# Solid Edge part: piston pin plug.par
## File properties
Author: Robert a Rhodes jr
Template: Normal.par
Last saved by: Cadcim
Revision: 5
Application: Solid Edge
Accuracy: 0.99
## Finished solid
Body 1: solid body, 6 faces, 5 edges, 0 vertices.
  Faces by surface: plane 3, cylinder 2, torus 1
  Edges by curve: circle 5
Bounding box of the edges (mm; curved faces can reach further): 22.000 x 22.000 x 15.000, from (-11, -11, -12) to (11, 11, 3).
Cylindrical faces by radius (mm): R5.5 x1, R11 x1
Toroidal faces (ring radius, tube radius in mm): R9 r2 x1
Planar faces by outward normal: +z 1, -z 2
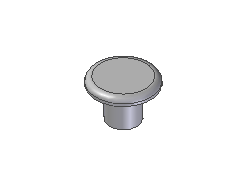
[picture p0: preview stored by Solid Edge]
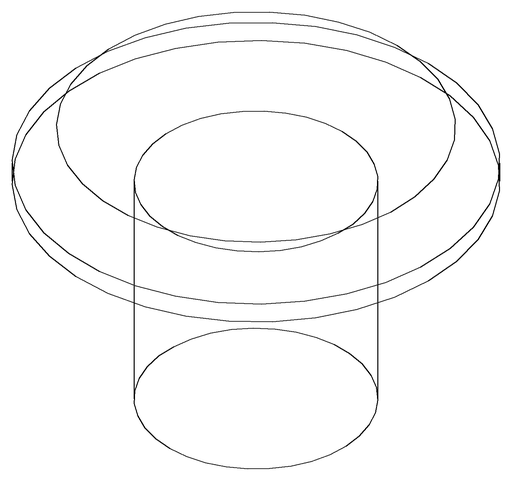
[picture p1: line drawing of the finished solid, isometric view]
